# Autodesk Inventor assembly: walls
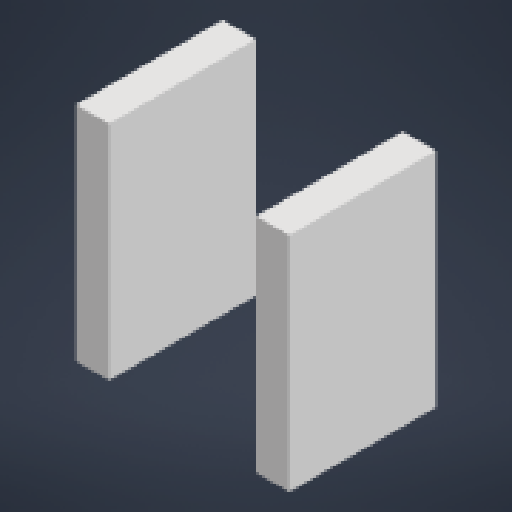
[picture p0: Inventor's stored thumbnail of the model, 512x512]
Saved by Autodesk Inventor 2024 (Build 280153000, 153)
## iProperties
Created: 2023-09
Part Number: walls
Document SubType Name: Assembly
Designer: mammothbane
Author: mammothbane
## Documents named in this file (2)
- \\caemlyn.p.hs.npry.dev\media\modeling\mit\mas.863\walls.iam
- \\caemlyn.p.hs.npry.dev\media\modeling\mit\mas.863\side_wall.ipt
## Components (2 placed, 1 different names)
1. side_wall:1 — Mate:1
2. side_wall:2 — Mate:2
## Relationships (2: Mate 2)
- Mate:1: side_wall:1
- Mate:2: side_wall:2
